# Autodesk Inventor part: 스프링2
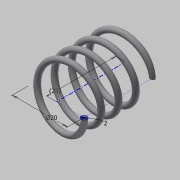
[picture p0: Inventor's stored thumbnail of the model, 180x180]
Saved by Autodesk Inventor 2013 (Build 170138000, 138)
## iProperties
Created: 2016-07
Part Number: 스프링2
Material: 스테인리스강
Document SubType Name: Modeling
Designer: dgall
Density: 8.08 g/cm^3
Mass: 6.26715 g
Surface Area: 15.7465 cm^2
Volume: 0.775637 cm^3
Author: dgall
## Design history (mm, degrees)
sketch "스케치1"
  geometry: L1 (0, 0)-(10, 0); L2 (10, 0)-(10, 22.5); L3 (10, 22.5)-(0, 22.5); L4 (0, 22.5)-(0, 0); C1 r 1 at (10, 0)
  constraints: 8 end point, 2 parallel, 1 centre point, 1 coincident, 1 horizontal, 1 perpendicular
  dimensions: "d0" = 2 diameter of C1; "d2" = 22.5 distance of L3.end L1.start (derived); "d3" = 20 diameter of L2 L4
feature "코일1" sketch "스케치1" pitch "d4" = 10; turns "d6" = 4; dims "d5" = 22.5 (= d2), "d7" = 0, angle "d8" = 90 deg, angle "d9" = 90 deg, "d10" = 0, "d11" = 0
feature "분할1"
node "작업 평면1"
feature "분할2"
node "솔리드1"
